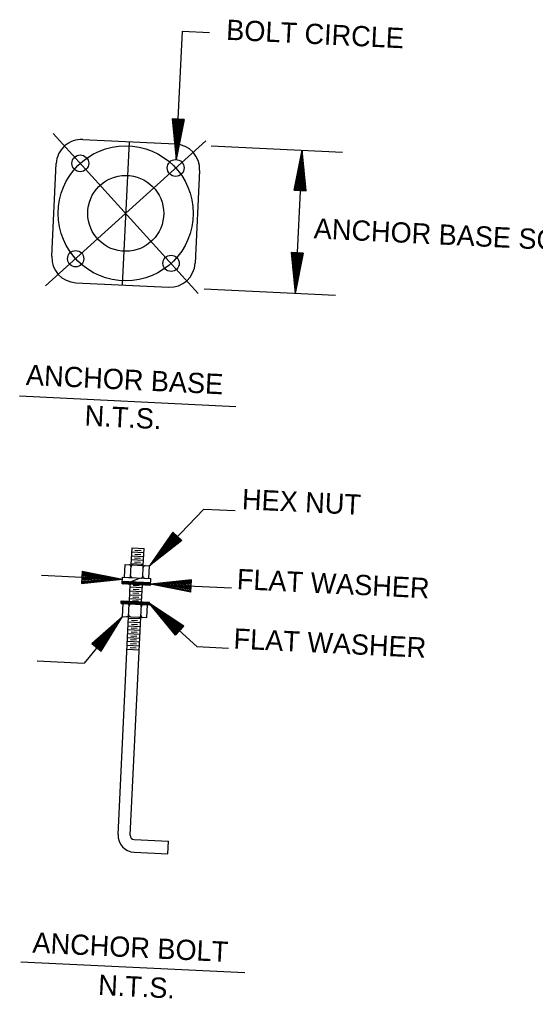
# Model space of a CAD drawing. Extents: x 661018 to 663325, y 642537 to 643074.
# Drawn here: x 661979.1 to 662064.8, y 642757.3 to 642920.1 of the extents above; entities that cross this region are included whole.
import ezdxf

# ---------------------------------------------------------------- set-up
doc = ezdxf.new("R2010")
doc.units = 0
doc.layers.add('R_Dimension', color=7, linetype='Continuous')

msp = doc.modelspace()

# ---------------------------------------------------------------- linework, layer by layer
at = {"layer": 'R_Dimension'}
for p, q in [((662005.11, 642896.84), (662006.15, 642918.22)), ((662006.15, 642918.22), (662010.67, 642918)), ((662004.43, 642903.62), (662005.11, 642896.84)), ((662006.45, 642903.52), (662004.43, 642903.62)), ((662004.6, 642903.61), (662005.17, 642897.96)), ((662004.77, 642903.6), (662005.22, 642899.12)), ((662004.94, 642903.59), (662005.28, 642900.24)), ((662005.11, 642903.58), (662005.33, 642901.38)), ((662006.45, 642903.52), (662005.11, 642896.84)), ((662006.28, 642903.53), (662005.17, 642897.96)), ((662006.11, 642903.54), (662005.22, 642899.12)), ((662005.28, 642903.58), (662005.39, 642902.5)), ((662005.94, 642903.54), (662005.28, 642900.24)), ((662005.77, 642903.55), (662005.33, 642901.38)), ((662005.6, 642903.56), (662005.39, 642902.5)), ((662008.8, 642874.58), (661984.65, 642901.2)), ((661983.42, 642875.81), (662010.03, 642899.96)), ((661989.59, 642900.18), (662005.02, 642899.43)), ((661997.31, 642899.81), (661996.15, 642875.97)), ((662010.91, 642899.15), (662032.78, 642898.08)), ((662024.71, 642891.73), (662026.05, 642898.41)), ((662026.05, 642898.41), (662024.89, 642874.57)), ((662026.73, 642891.63), (662026.05, 642898.41)), ((662024.88, 642891.72), (662026, 642897.29)), ((662026.57, 642891.64), (662026, 642897.29)), ((661984.43, 642880.76), (661985.18, 642896.18)), ((662009.02, 642895.02), (662008.27, 642879.6)), ((662025.05, 642891.71), (662025.94, 642896.13)), ((662025.22, 642891.71), (662025.89, 642895.01)), ((662026.23, 642891.66), (662025.89, 642895.01)), ((662026.39, 642891.65), (662025.94, 642896.13)), ((662025.4, 642891.7), (662025.83, 642893.87)), ((662026.05, 642891.66), (662025.83, 642893.87)), ((662024.71, 642891.73), (662026.73, 642891.63)), ((662025.57, 642891.69), (662025.78, 642892.74)), ((662025.88, 642891.67), (662025.78, 642892.74)), ((662024.21, 642881.35), (662024.89, 642874.57)), ((662026.23, 642881.26), (662024.21, 642881.35)), ((662024.38, 642881.35), (662024.95, 642875.7)), ((662024.55, 642881.34), (662025, 642876.86)), ((662024.72, 642881.33), (662025.06, 642877.98)), ((662024.89, 642881.32), (662025.11, 642879.12)), ((662026.23, 642881.26), (662024.89, 642874.57)), ((662026.06, 642881.26), (662024.95, 642875.7)), ((662025.89, 642881.27), (662025, 642876.86)), ((662025.06, 642881.31), (662025.17, 642880.24)), ((662025.72, 642881.28), (662025.06, 642877.98)), ((662025.55, 642881.29), (662025.11, 642879.12)), ((662025.38, 642881.3), (662025.17, 642880.24)), ((661988.44, 642876.34), (662003.86, 642875.6)), ((662009.75, 642875.31), (662031.62, 642874.25)), ((662015.05, 642855.71), (661979.09, 642857.45)), ((662000.67, 642829.26), (662009.69, 642838.68)), ((662009.69, 642838.68), (662014.94, 642838.43)), ((662004.58, 642834.84), (662000.67, 642829.26)), ((662004.7, 642834.72), (662001.45, 642830.07)), ((662004.83, 642834.6), (662002.25, 642830.91)), ((662004.95, 642834.49), (662003.02, 642831.73)), ((662006.05, 642833.44), (662004.58, 642834.84)), ((662006.05, 642833.44), (662000.67, 642829.26)), ((662005.92, 642833.56), (662001.45, 642830.07)), ((662005.8, 642833.68), (662002.25, 642830.91)), ((662005.68, 642833.8), (662003.02, 642831.73)), ((662005.07, 642834.37), (662003.81, 642832.55)), ((662005.55, 642833.92), (662003.81, 642832.55)), ((662005.2, 642834.25), (662004.58, 642833.37)), ((662005.43, 642834.03), (662004.58, 642833.37)), ((661997.64, 642829.4), (661997.78, 642832.21)), ((661997.75, 642831.56), (661999.77, 642831.46)), ((661997.78, 642832.21), (661999.8, 642832.11)), ((661998.24, 642831.2), (661999.25, 642831.15)), ((661998.27, 642831.85), (661999.28, 642831.8)), ((661999.66, 642829.31), (661999.8, 642832.11)), ((661997.65, 642829.62), (661999.67, 642829.52)), ((661997.68, 642830.27), (661999.7, 642830.17)), ((661997.72, 642830.91), (661999.74, 642830.82)), ((661998.17, 642829.91), (661999.18, 642829.86)), ((661998.2, 642830.55), (661999.21, 642830.5)), ((661989.5, 642828.34), (661989.4, 642826.32)), ((661989.48, 642828), (661993.9, 642827.12)), ((661989.49, 642828.17), (661995.05, 642827.06)), ((661989.5, 642828.34), (661996.18, 642827.01)), ((661996.53, 642827.33), (661996.63, 642829.45)), ((661996.63, 642829.45), (662000.67, 642829.26)), ((661997.54, 642827.28), (661997.64, 642829.4)), ((661999.56, 642827.18), (661999.66, 642829.31)), ((662000.57, 642827.13), (662000.67, 642829.26)), ((661982.72, 642827.66), (661996.18, 642827.01)), ((661989.4, 642826.32), (661996.18, 642827.01)), ((661989.41, 642826.66), (661993.9, 642827.12)), ((661989.41, 642826.49), (661995.05, 642827.06)), ((661989.42, 642826.83), (661992.77, 642827.17)), ((661989.43, 642827), (661991.63, 642827.23)), ((661989.44, 642827.17), (661990.51, 642827.28)), ((661989.45, 642827.49), (661990.51, 642827.28)), ((661989.46, 642827.66), (661991.63, 642827.23)), ((661989.47, 642827.83), (661992.77, 642827.17)), ((661996.14, 642826.22), (661996.19, 642827.34)), ((661996.14, 642826.24), (661996.59, 642826.65)), ((661996.15, 642826.48), (661996.35, 642826.66)), ((661996.16, 642826.67), (662000.87, 642826.44)), ((661996.19, 642827.34), (662000.9, 642827.11)), ((661996.35, 642826.21), (661996.82, 642826.64)), ((661996.59, 642826.2), (661997.06, 642826.62)), ((661996.83, 642826.19), (661997.3, 642826.61)), ((661997.07, 642826.17), (661997.54, 642826.6)), ((661997.31, 642826.16), (661997.78, 642826.59)), ((661997.51, 642826.6), (661999.02, 642827.18)), ((661997.54, 642826.15), (661998.01, 642826.58)), ((661997.78, 642826.14), (661998.25, 642826.57)), ((661998.02, 642826.13), (661998.49, 642826.55)), ((661998.26, 642826.12), (661998.73, 642826.54)), ((661998.5, 642826.1), (661998.97, 642826.53)), ((661998.73, 642826.09), (661999.2, 642826.52)), ((661998.97, 642826.08), (661999.44, 642826.51)), ((661999.21, 642826.07), (661999.68, 642826.5)), ((661999.45, 642826.06), (661999.92, 642826.49)), ((661999.69, 642826.05), (662000.16, 642826.47)), ((661999.92, 642826.04), (662000.39, 642826.46)), ((662000.16, 642826.02), (662000.63, 642826.45)), ((662000.4, 642826.01), (662000.87, 642826.44)), ((662000.85, 642825.99), (662000.9, 642827.11)), ((662007.64, 642826.9), (662000.86, 642826.21)), ((662007.63, 642826.73), (662001.99, 642826.16)), ((662007.62, 642826.56), (662003.14, 642826.1)), ((662007.62, 642826.39), (662004.26, 642826.05)), ((662007.54, 642824.88), (662007.64, 642826.9)), ((662000.85, 642825.99), (661996.14, 642826.22)), ((661997.35, 642823.35), (661997.48, 642826.15)), ((661997.43, 642825.09), (661999.45, 642824.99)), ((661997.46, 642825.74), (661999.48, 642825.64)), ((661997.92, 642824.73), (661998.93, 642824.68)), ((661997.95, 642825.38), (661998.96, 642825.33)), ((661997.98, 642826.02), (661998.99, 642825.97)), ((661999.37, 642823.25), (661999.5, 642826.06)), ((662000.64, 642826), (662000.86, 642826.2)), ((662000.86, 642826.21), (662014.32, 642825.56)), ((662007.54, 642824.88), (662000.86, 642826.21)), ((662007.55, 642825.05), (662001.99, 642826.16)), ((662007.56, 642825.22), (662003.14, 642826.1)), ((662007.57, 642825.39), (662004.26, 642826.05)), ((662007.61, 642826.22), (662005.4, 642825.99)), ((662007.58, 642825.56), (662005.4, 642825.99)), ((662007.6, 642826.05), (662006.53, 642825.94)), ((662007.58, 642825.73), (662006.53, 642825.94)), ((661995.98, 642822.97), (661996, 642823.41)), ((661995.99, 642823.19), (661996.23, 642823.4)), ((661996, 642823.41), (662000.71, 642823.19)), ((661996, 642822.97), (661996.47, 642823.39)), ((661996.24, 642822.95), (661996.71, 642823.38)), ((661996.47, 642822.94), (661996.94, 642823.37)), ((661996.71, 642822.93), (661997.18, 642823.36)), ((661996.95, 642822.92), (661997.42, 642823.35)), ((661997.19, 642822.91), (661997.66, 642823.33)), ((661997.37, 642823.8), (661999.39, 642823.7)), ((661997.4, 642824.44), (661999.42, 642824.34)), ((661997.43, 642822.9), (661997.9, 642823.32)), ((661997.66, 642822.88), (661998.13, 642823.31)), ((661997.86, 642823.43), (661998.87, 642823.39)), ((661997.89, 642824.08), (661998.9, 642824.03)), ((661997.9, 642822.87), (661998.37, 642823.3)), ((661998.14, 642822.86), (661998.61, 642823.29)), ((661998.38, 642822.85), (661998.85, 642823.28)), ((661998.62, 642822.84), (661999.09, 642823.26)), ((661998.85, 642822.83), (661999.32, 642823.25)), ((661999.09, 642822.81), (661999.56, 642823.24)), ((661999.33, 642822.8), (661999.8, 642823.23)), ((661999.57, 642822.79), (662000.04, 642823.22)), ((661999.81, 642822.78), (662000.28, 642823.21)), ((662000.04, 642822.77), (662000.51, 642823.2)), ((662000.28, 642822.76), (662000.71, 642823.15)), ((662000.69, 642822.74), (662000.71, 642823.19)), ((661995.98, 642822.97), (662000.69, 642822.74)), ((661996.21, 642820.82), (661996.32, 642822.95)), ((661997.22, 642820.77), (661997.33, 642822.9)), ((661999.24, 642820.68), (661999.35, 642822.8)), ((662000.25, 642820.63), (662000.36, 642822.75)), ((662000.52, 642822.75), (662000.7, 642822.91)), ((662000.7, 642822.96), (662008.58, 642815.81)), ((662005.01, 642817.69), (662000.7, 642822.96)), ((662006.37, 642819.18), (662000.7, 642822.96)), ((662005.13, 642817.81), (662001.54, 642822.21)), ((662006.26, 642819.06), (662001.54, 642822.21)), ((662006.14, 642818.93), (662002.4, 642821.43)), ((662005.24, 642817.94), (662002.4, 642821.43)), ((661996.21, 642820.82), (661989.8, 642813.04)), ((661991.1, 642816.32), (661996.21, 642820.82)), ((661991.23, 642816.21), (661995.49, 642819.96)), ((661992.52, 642815.12), (661995.49, 642819.96)), ((661992.65, 642815.02), (661996.21, 642820.82)), ((661995.46, 642784.53), (661997.22, 642820.77)), ((661996.21, 642820.82), (662000.25, 642820.63)), ((661997.18, 642819.91), (661999.2, 642819.81)), ((661997.21, 642820.56), (661999.23, 642820.46)), ((661997.48, 642784.41), (661999.24, 642820.68)), ((661997.7, 642820.2), (661998.71, 642820.15)), ((662005.36, 642818.06), (662003.23, 642820.67)), ((662006.03, 642818.81), (662003.23, 642820.67)), ((662005.92, 642818.68), (662004.07, 642819.91)), ((662005.47, 642818.19), (662004.07, 642819.91)), ((661991.36, 642816.1), (661994.74, 642819.08)), ((661991.49, 642815.99), (661994.02, 642818.22)), ((661992.26, 642815.34), (661994.02, 642818.22)), ((661992.39, 642815.24), (661994.74, 642819.08)), ((661997.12, 642818.62), (661999.14, 642818.52)), ((661997.15, 642819.26), (661999.17, 642819.17)), ((661997.61, 642818.26), (661998.62, 642818.21)), ((661997.64, 642818.9), (661998.65, 642818.85)), ((661997.67, 642819.55), (661998.68, 642819.5)), ((662005.8, 642818.55), (662004.91, 642819.15)), ((662005.59, 642818.32), (662004.91, 642819.15)), ((662005.01, 642817.69), (662006.37, 642819.18)), ((661991.63, 642815.88), (661993.29, 642817.34)), ((661992.13, 642815.45), (661993.29, 642817.34)), ((661997.02, 642816.68), (661999.04, 642816.58)), ((661997.06, 642817.32), (661999.08, 642817.23)), ((661997.09, 642817.97), (661999.11, 642817.87)), ((661997.54, 642816.96), (661998.55, 642816.91)), ((661997.58, 642817.61), (661998.59, 642817.56)), ((661991.1, 642816.32), (661992.65, 642815.02)), ((661991.76, 642815.77), (661992.56, 642816.48)), ((661992, 642815.56), (661992.56, 642816.48)), ((661996.96, 642815.38), (661998.98, 642815.28)), ((661996.99, 642816.03), (661999.01, 642815.93)), ((661997.48, 642815.67), (661998.49, 642815.62)), ((661997.51, 642816.32), (661998.52, 642816.27)), ((662008.58, 642815.81), (662013.83, 642815.55)), ((661982.03, 642813.42), (661989.8, 642813.04)), ((661998.12, 642783.7), (662003.84, 642783.42)), ((662003.74, 642781.32), (662003.84, 642783.42)), ((661998.13, 642781.59), (662003.74, 642781.32)), ((662016.51, 642761.52), (661979.32, 642763.32))]:
    msp.add_line(p, q, dxfattribs=at)
for centre, radius in [((661996.73, 642887.89), 11.23), ((661989.18, 642896.21), 1.4), ((662005.04, 642895.44), 1.4), ((661996.73, 642887.89), 6.32), ((661988.41, 642880.34), 1.35), ((662004.27, 642879.57), 1.35)]:
    msp.add_circle(centre, radius, dxfattribs=at)
for centre, radius, start, end in [((661989.39, 642895.98), 4.21, 87.2199, 177.2199), ((662004.81, 642895.23), 4.21, 357.2199, 87.2199), ((661988.64, 642880.55), 4.21, 177.2199, 267.2199), ((662004.06, 642879.8), 4.21, 267.2199, 357.2199), ((661997.29, 642829.08), 0.337, 357.2199, 87.2199), ((661997.96, 642829.05), 0.337, 87.2199, 177.2199), ((661999.31, 642828.99), 0.337, 357.2199, 87.2199), ((661999.98, 642828.95), 0.337, 87.2199, 177.2199), ((661997.22, 642827.63), 0.337, 267.2199, 357.2199), ((661997.89, 642827.6), 0.337, 177.2199, 267.2199), ((661999.24, 642827.53), 0.337, 267.2199, 357.2199), ((661999.91, 642827.5), 0.337, 177.2199, 267.2199), ((661996.97, 642822.58), 0.337, 357.2199, 87.2199), ((661997.65, 642822.55), 0.337, 87.2199, 177.2199), ((661998.99, 642822.48), 0.337, 357.2199, 87.2199), ((661999.67, 642822.45), 0.337, 87.2199, 177.2199), ((661996.9, 642821.13), 0.337, 267.2199, 357.2199), ((661997.58, 642821.09), 0.337, 177.2199, 267.2199), ((661998.92, 642821.03), 0.337, 267.2199, 357.2199), ((661999.6, 642821), 0.337, 177.2199, 267.2199), ((661998.27, 642784.4), 2.81, 177.2199, 267.2199), ((661998.15, 642784.37), 0.674, 177.2199, 267.2199)]:
    msp.add_arc(centre, radius, start, end, dxfattribs=at)

# ---------------------------------------------------------------- texts
for s, height, p in [('BOLT CIRCLE', 3.3692, (662013.38, 642916.78)), ('ANCHOR BASE SQUARE', 3.3692, (662027.94, 642883.73)), ('ANCHOR BASE', 3.3692, (661980.1, 642859.36)), ('N.T.S.', 3.369, (661989.84, 642852.59)), ('HEX NUT', 3.369, (662016, 642838.67)), ('FLAT WASHER', 3.3692, (662015.15, 642825.38)), ('FLAT WASHER', 3.3692, (662014.6, 642815.48)), ('ANCHOR BOLT', 3.3692, (661981.18, 642764.9)), ('N.T.S.', 3.369, (661992.09, 642757.86))]:
    msp.add_text(s, height=height, rotation=357.2199, dxfattribs=at).set_placement(p)

doc.saveas('drawing.dxf')
